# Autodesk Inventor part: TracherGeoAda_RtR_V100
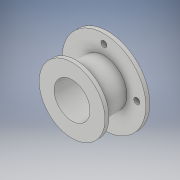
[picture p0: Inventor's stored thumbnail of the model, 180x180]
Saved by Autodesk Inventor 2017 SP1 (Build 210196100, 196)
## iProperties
Part Number: TracherGeoAda_RtR_V100
Material: Generisch
Document SubType Name: Modeling
Designer: haesner
Density: 1 g/cm^3
Appearance: Vorgabe
Part Number: TracherGeoAda_RtR_V100_3D-Druck
Author: haesner
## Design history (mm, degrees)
sketch "Skizze1"
  geometry: C1 r 9 at (0, 0); 1 further point
  constraints: 1 centre point, 1 coincident
  dimensions: "d0" = 18 diameter of C1
workplane "Arbeitsebene1"
sketch "Skizze2"
  geometry: C1 r 8.5 at (0, 0); 1 further point
  constraints: 1 centre point, 1 coincident
  dimensions: "d2" = 17 diameter of C1
feature "Erhebung1" sketch "Skizze2" dims "d3" = 0, "d4" = 90 deg, "d5" = 0, "d6" = 90 deg
feature "Wandung1" dims "d7" = 3
sketch "Skizze3"
  geometry: C1 r 21 at (0, 0); C2 r 11.501 at (0, 0) reference; 1 further point
  constraints: 1 centre point, 1 coincident
  dimensions: "d8" = 42 diameter of C1
extrude "Extrusion1" join sketch "Skizze3" distance "d9" = 2; taper "d10" = 0 deg
sketch "Skizze4"
  geometry: C1 r 16.5 at (0, 0); C2 r 9 at (0, 0) reference; 1 further point
  constraints: 1 centre point, 1 coincident
  dimensions: "d11" = 33 diameter of C1
extrude "Extrusion2" join sketch "Skizze4" distance "d12" = 2; taper "d13" = 0 deg
sketch "Skizze5"
  geometry: L1 (-16.5, 0)-(0, -16.5); L2 (0, -16.5)-(16.5, 0); L3 (16.5, 0)-(0, 16.5); L4 (0, 16.5)-(-16.5, 0); L5 (-29.4, 0)-(29.4, 0) reference; L6 (0, 29.4)-(0, -29.4) reference; 1 further point
  constraints: 8 end point, 3 point on line, 2 parallel, 2 perpendicular
  dimensions: "d14" = 16.5 distance from line of L6 L1.start
hole "Bohrung1" sketch "Skizze5" at (-16.5, 0), (0, 16.5), (16.5, 0), (0, -16.5) diameter "d15" = 3; stored, may be unused: countersink angle "d19" = 90 deg, drill point angle "d21" = 118 deg; dims "d16" = 6, "d17" = 4, "d18" = 2, "d20" = 8
node "Volumenkörper1"
other parameters: "d1" = 18
